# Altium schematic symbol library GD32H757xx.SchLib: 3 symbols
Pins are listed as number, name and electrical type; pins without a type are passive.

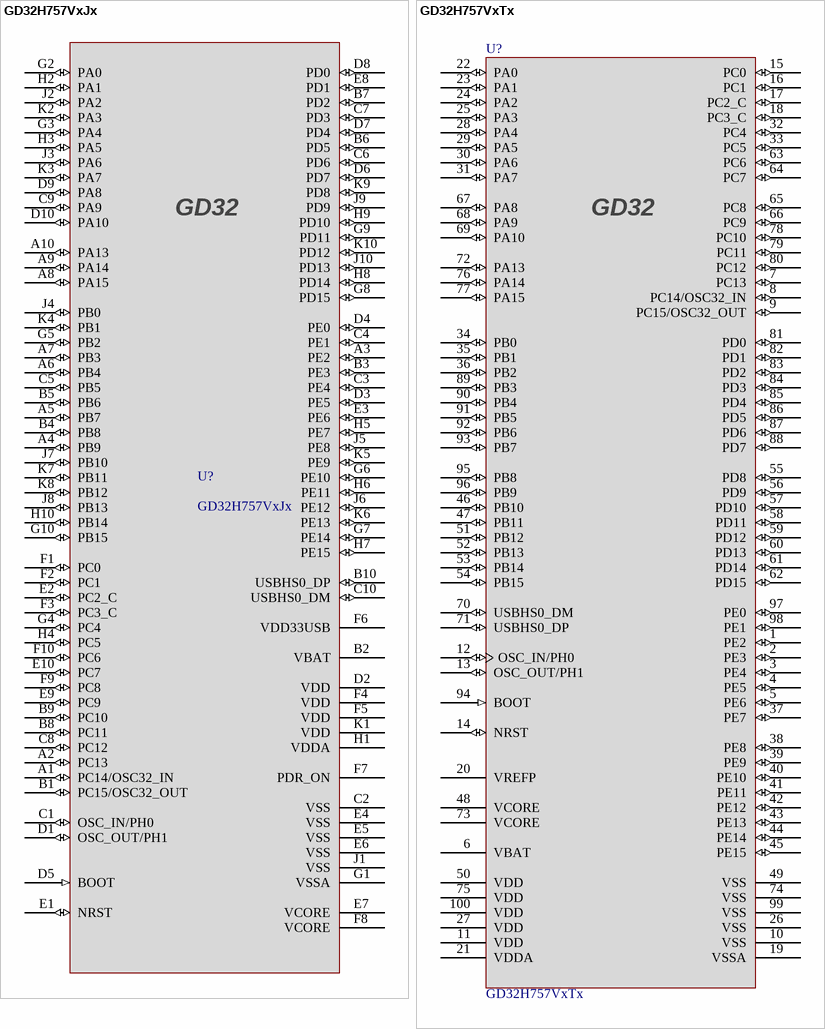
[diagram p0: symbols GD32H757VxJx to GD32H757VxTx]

## GD32H757VxJx
designator U?
footprint BGA100_8X8X1.1
pins: A1 PC14/OSC32_IN (io), A2 PC13 (io), A3 PE2 (io), A4 PB9 (io), A5 PB7 (io), A6 PB4 (io), A7 PB3 (io), A8 PA15 (io), A9 PA14 (io), A10 PA13 (io), B1 PC15/OSC32_OUT (io), B2 VBAT (power), B3 PE3 (io), B4 PB8 (io), B5 PB6 (io), B6 PD5 (io), B7 PD2 (io), B8 PC11 (io), B9 PC10 (io), B10 USBHS0_DP (io), C1 OSC_IN/PH0 (io), C2 VSS (power), C3 PE4 (io), C4 PE1 (io), C5 PB5 (io), C6 PD6 (io), C7 PD3 (io), C8 PC12 (io), C9 PA9 (io), C10 USBHS0_DM (io), D1 OSC_OUT/PH1 (io), D2 VDD (power), D3 PE5 (io), D4 PE0 (io), D5 BOOT (in), D6 PD7 (io), D7 PD4 (io), D8 PD0 (io), D9 PA8 (io), D10 PA10 (io), E1 NRST (io), E2 PC2_C (io), E3 PE6 (io), E4 VSS (power), E5 VSS (power), E6 VSS (power), E7 VCORE (power), E8 PD1 (io), E9 PC9 (io), E10 PC7 (io), F1 PC0 (io), F2 PC1 (io), F3 PC3_C (io), F4 VDD (power), F5 VDD (power), F6 VDD33USB (power), F7 PDR_ON (power), F8 VCORE (power), F9 PC8 (io), F10 PC6 (io), G1 VSSA (power), G2 PA0 (io), G3 PA4 (io), G4 PC4 (io), G5 PB2 (io), G6 PE10 (io), G7 PE14 (io), G8 PD15 (io), G9 PD11 (io), G10 PB15 (io), H1 VDDA (power), H2 PA1 (io), H3 PA5 (io), H4 PC5 (io), H5 PE7 (io), H6 PE11 (io), H7 PE15 (io), H8 PD14 (io), H9 PD10 (io), H10 PB14 (io), J1 VSS (power), J2 PA2 (io), J3 PA6 (io), J4 PB0 (io), J5 PE8 (io), J6 PE12 (io), J7 PB10 (io), J8 PB13 (io), J9 PD9 (io), J10 PD13 (io), K1 VDD (power), K2 PA3 (io), K3 PA7 (io), K4 PB1 (io), K5 PE9 (io), K6 PE13 (io), K7 PB11 (io), K8 PB12 (io), K9 PD8 (io), K10 PD12 (io)

## GD32H757VxTx
designator U?
footprint LQFP100_14x14x1.6
pins: 1 PE2 (io), 2 PE3 (io), 3 PE4 (io), 4 PE5 (io), 5 PE6 (io), 6 VBAT (power), 7 PC13 (io), 8 PC14/OSC32_IN (io), 9 PC15/OSC32_OUT (io), 10 VSS (power), 11 VDD (power), 12 OSC_IN/PH0 (io), 13 OSC_OUT/PH1 (io), 14 NRST (io), 15 PC0 (io), 16 PC1 (io), 17 PC2_C (io), 18 PC3_C (io), 19 VSSA (power), 20 VREFP (power), 21 VDDA (power), 22 PA0 (io), 23 PA1 (io), 24 PA2 (io), 25 PA3 (io), 26 VSS (power), 27 VDD (power), 28 PA4 (io), 29 PA5 (io), 30 PA6 (io), 31 PA7 (io), 32 PC4 (io), 33 PC5 (io), 34 PB0 (io), 35 PB1 (io), 36 PB2 (io), 37 PE7 (io), 38 PE8 (io), 39 PE9 (io), 40 PE10 (io), 41 PE11 (io), 42 PE12 (io), 43 PE13 (io), 44 PE14 (io), 45 PE15 (io), 46 PB10 (io), 47 PB11 (io), 48 VCORE (power), 49 VSS (power), 50 VDD (power), 51 PB12 (io), 52 PB13 (io), 53 PB14 (io), 54 PB15 (io), 55 PD8 (io), 56 PD9 (io), 57 PD10 (io), 58 PD11 (io), 59 PD12 (io), 60 PD13 (io), 61 PD14 (io), 62 PD15 (io), 63 PC6 (io), 64 PC7 (io), 65 PC8 (io), 66 PC9 (io), 67 PA8 (io), 68 PA9 (io), 69 PA10 (io), 70 USBHS0_DM (io), 71 USBHS0_DP (io), 72 PA13 (io), 73 VCORE (power), 74 VSS (power), 75 VDD (power), 76 PA14 (io), 77 PA15 (io), 78 PC10 (io), 79 PC11 (io), 80 PC12 (io), 81 PD0 (io), 82 PD1 (io), 83 PD2 (io), 84 PD3 (io), 85 PD4 (io), 86 PD5 (io), 87 PD6 (io), 88 PD7 (io), 89 PB3 (io), 90 PB4 (io), 91 PB5 (io), 92 PB6 (io), 93 PB7 (io), 94 BOOT (in), 95 PB8 (io), 96 PB9 (io), 97 PE0 (io), 98 PE1 (io), 99 VSS (power), 100 VDD (power)

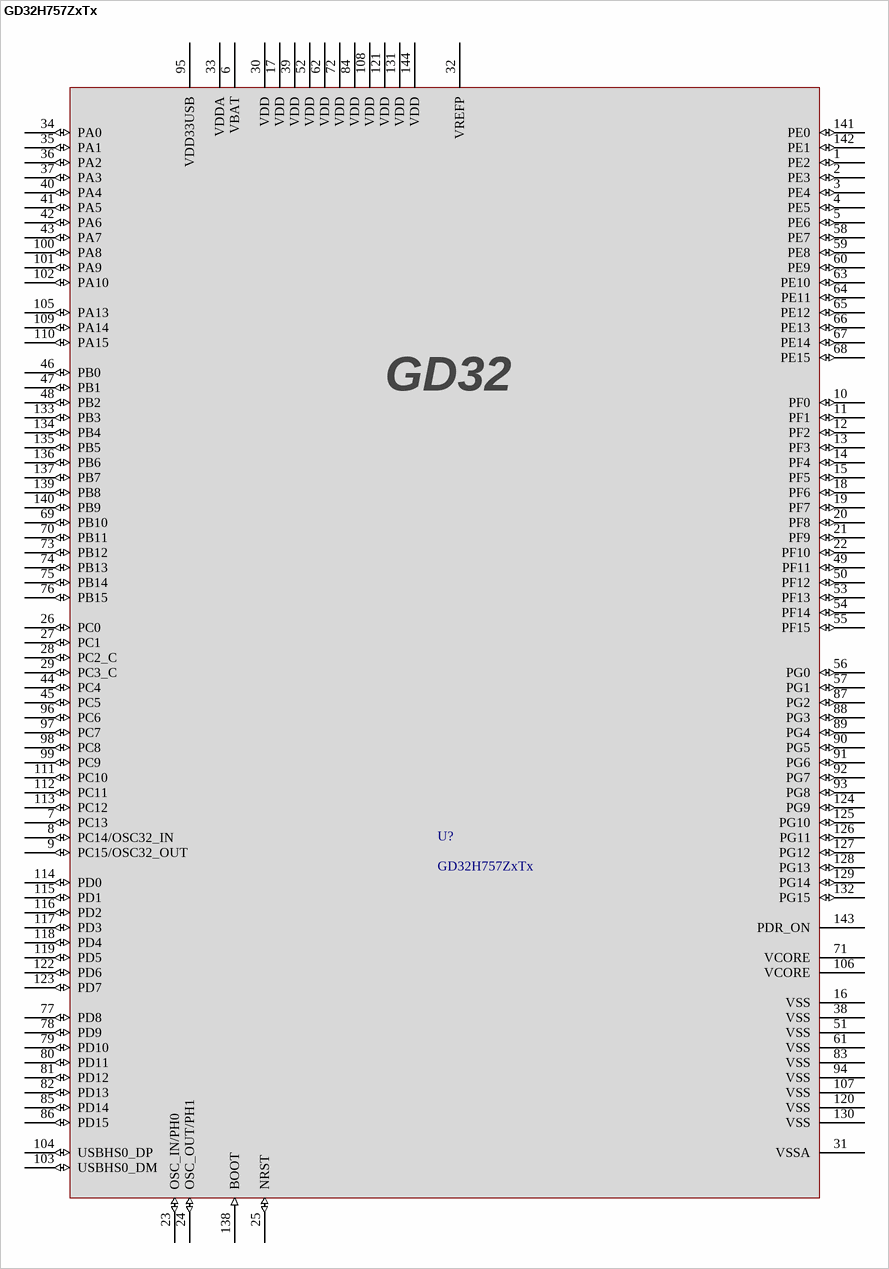
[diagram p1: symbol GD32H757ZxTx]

## GD32H757ZxTx
designator U?
footprint LQFP144_20x20X1.6
pins: 1 PE2 (io), 2 PE3 (io), 3 PE4 (io), 4 PE5 (io), 5 PE6 (io), 6 VBAT (power), 7 PC13 (io), 8 PC14/OSC32_IN (io), 9 PC15/OSC32_OUT (io), 10 PF0 (io), 11 PF1 (io), 12 PF2 (io), 13 PF3 (io), 14 PF4 (io), 15 PF5 (io), 16 VSS (power), 17 VDD (power), 18 PF6 (io), 19 PF7 (io), 20 PF8 (io), 21 PF9 (io), 22 PF10 (io), 23 OSC_IN/PH0 (io), 24 OSC_OUT/PH1 (io), 25 NRST (io), 26 PC0 (io), 27 PC1 (io), 28 PC2_C (io), 29 PC3_C (io), 30 VDD (power), 31 VSSA (power), 32 VREFP (power), 33 VDDA (power), 34 PA0 (io), 35 PA1 (io), 36 PA2 (io), 37 PA3 (io), 38 VSS (power), 39 VDD (power), 40 PA4 (io), 41 PA5 (io), 42 PA6 (io), 43 PA7 (io), 44 PC4 (io), 45 PC5 (io), 46 PB0 (io), 47 PB1 (io), 48 PB2 (io), 49 PF11 (io), 50 PF12 (io), 51 VSS (power), 52 VDD (power), 53 PF13 (io), 54 PF14 (io), 55 PF15 (io), 56 PG0 (io), 57 PG1 (io), 58 PE7 (io), 59 PE8 (io), 60 PE9 (io), 61 VSS (power), 62 VDD (power), 63 PE10 (io), 64 PE11 (io), 65 PE12 (io), 66 PE13 (io), 67 PE14 (io), 68 PE15 (io), 69 PB10 (io), 70 PB11 (io), 71 VCORE (power), 72 VDD (power), 73 PB12 (io), 74 PB13 (io), 75 PB14 (io), 76 PB15 (io), 77 PD8 (io), 78 PD9 (io), 79 PD10 (io), 80 PD11 (io), 81 PD12 (io), 82 PD13 (io), 83 VSS (power), 84 VDD (power), 85 PD14 (io), 86 PD15 (io), 87 PG2 (io), 88 PG3 (io), 89 PG4 (io), 90 PG5 (io), 91 PG6 (io), 92 PG7 (io), 93 PG8 (io), 94 VSS (power), 95 VDD33USB (power), 96 PC6 (io), 97 PC7 (io), 98 PC8 (io), 99 PC9 (io), 100 PA8 (io), 101 PA9 (io), 102 PA10 (io), 103 USBHS0_DM (io), 104 USBHS0_DP (io), 105 PA13 (io), 106 VCORE (power), 107 VSS (power), 108 VDD (power), 109 PA14 (io), 110 PA15 (io), 111 PC10 (io), 112 PC11 (io), 113 PC12 (io), 114 PD0 (io), 115 PD1 (io), 116 PD2 (io), 117 PD3 (io), 118 PD4 (io), 119 PD5 (io), 120 VSS (power), 121 VDD (power), 122 PD6 (io), 123 PD7 (io), 124 PG9 (io), 125 PG10 (io), 126 PG11 (io), 127 PG12 (io), 128 PG13 (io), 129 PG14 (io), 130 VSS (power), 131 VDD (power), 132 PG15 (io), 133 PB3 (io), 134 PB4 (io), 135 PB5 (io), 136 PB6 (io), 137 PB7 (io), 138 BOOT (in), 139 PB8 (io), 140 PB9 (io), 141 PE0 (io), 142 PE1 (io), 143 PDR_ON (power), 144 VDD (power)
